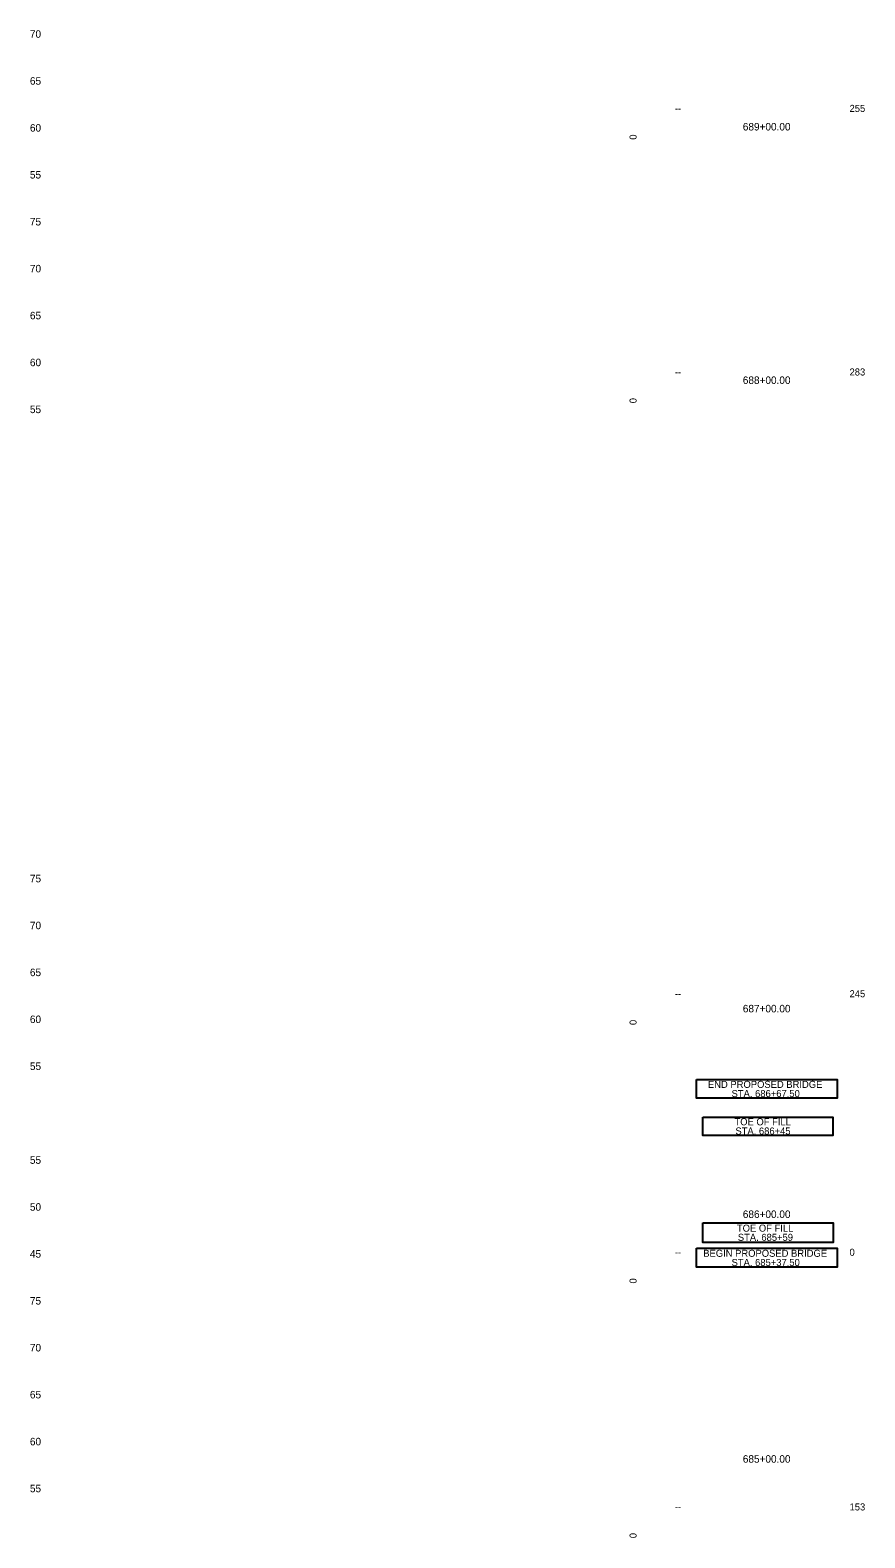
# Model space of a CAD drawing. Extents: x 952 to 1206, y 942 to 2399.
# Drawn here: x 1001.4 to 1090.5, y 1695.1 to 1855.8 of the extents above; entities that cross this region are included whole.
import ezdxf

# ---------------------------------------------------------------- set-up
doc = ezdxf.new("R2010")
doc.units = 0
for name, color, linetype in [('Default', 7, 'Continuous'), ('RD_SHT_TX', 7, 'Continuous'), ('RD_XS_TX_Elev_EX', 7, 'Continuous'), ('RD_XS_TX_Station', 7, 'Continuous')]:
    doc.layers.add(name, color=color, linetype=linetype)

msp = doc.modelspace()

# ---------------------------------------------------------------- linework, layer by layer
at = {"layer": 'RD_SHT_TX'}
for points in [[(1072.5, 1744), (1087.5, 1744), (1087.5, 1742), (1072.5, 1742)], [(1073.16, 1739.97), (1087.04, 1739.97), (1087.04, 1738.01), (1073.16, 1738.01)], [(1073.19, 1728.72), (1087.07, 1728.72), (1087.07, 1726.6), (1073.19, 1726.6)], [(1072.5, 1726), (1087.5, 1726), (1087.5, 1724), (1072.5, 1724)]]:
    msp.add_lwpolyline(points, close=True, dxfattribs=at)

# ---------------------------------------------------------------- texts
at = {"layer": 'Default'}
for s, p in [('255', (1088.82, 1847.1)), ('--', (1070.19, 1847.1)), ('--', (1070.19, 1819.01)), ('283', (1088.82, 1819.01)), ('--', (1070.19, 1752.75)), ('245', (1088.82, 1752.75)), ('0', (1088.82, 1725.2)), ('--', (1070.19, 1725.2)), ('--', (1070.19, 1698.06)), ('153', (1088.82, 1698.06))]:
    msp.add_text(s, height=0.75, dxfattribs=at).set_placement(p)
for p in [(1066.11, 1844.14), (1066.11, 1816.05), (1066.11, 1749.79), (1066.11, 1722.24), (1066.11, 1695.1)]:
    msp.add_text('0', height=0.75, rotation=90, dxfattribs=at).set_placement(p)
at = {"layer": 'RD_SHT_TX'}
for s, p in [('END PROPOSED BRIDGE', (1073.72, 1743.09)), ('STA. 686+67.50', (1076.24, 1742.11)), ('TOE OF FILL', (1076.55, 1739.1)), ('STA. 686+45', (1076.65, 1738.12)), ('TOE OF FILL', (1076.81, 1727.77)), ('STA. 685+59', (1076.91, 1726.79)), ('BEGIN PROPOSED BRIDGE', (1073.22, 1725.09)), ('STA. 685+37.50', (1076.24, 1724.11))]:
    msp.add_text(s, height=0.75, dxfattribs=at).set_placement(p)
at = {"layer": 'RD_XS_TX_Elev_EX'}
for s, p in [('70', (1001.42, 1855)), ('65', (1001.42, 1850)), ('60', (1001.42, 1845)), ('55', (1001.42, 1840)), ('75', (1001.42, 1835)), ('70', (1001.42, 1830)), ('65', (1001.42, 1825)), ('60', (1001.42, 1820)), ('55', (1001.42, 1815)), ('75', (1001.42, 1765)), ('70', (1001.42, 1760)), ('65', (1001.42, 1755)), ('60', (1001.42, 1750)), ('55', (1001.42, 1745)), ('55', (1001.42, 1735)), ('50', (1001.42, 1730)), ('45', (1001.42, 1725)), ('75', (1001.42, 1720)), ('70', (1001.42, 1715)), ('65', (1001.42, 1710)), ('60', (1001.42, 1705)), ('55', (1001.42, 1700))]:
    msp.add_text(s, height=0.8, dxfattribs=at).set_placement(p)
at = {"layer": 'RD_XS_TX_Station'}
for s, p in [('689+00.00', (1077.44, 1845.12)), ('688+00.00', (1077.44, 1818.11)), ('687+00.00', (1077.44, 1751.14)), ('686+00.00', (1077.44, 1729.23)), ('685+00.00', (1077.44, 1703.15))]:
    msp.add_text(s, height=0.8, dxfattribs=at).set_placement(p)

doc.saveas('drawing.dxf')
